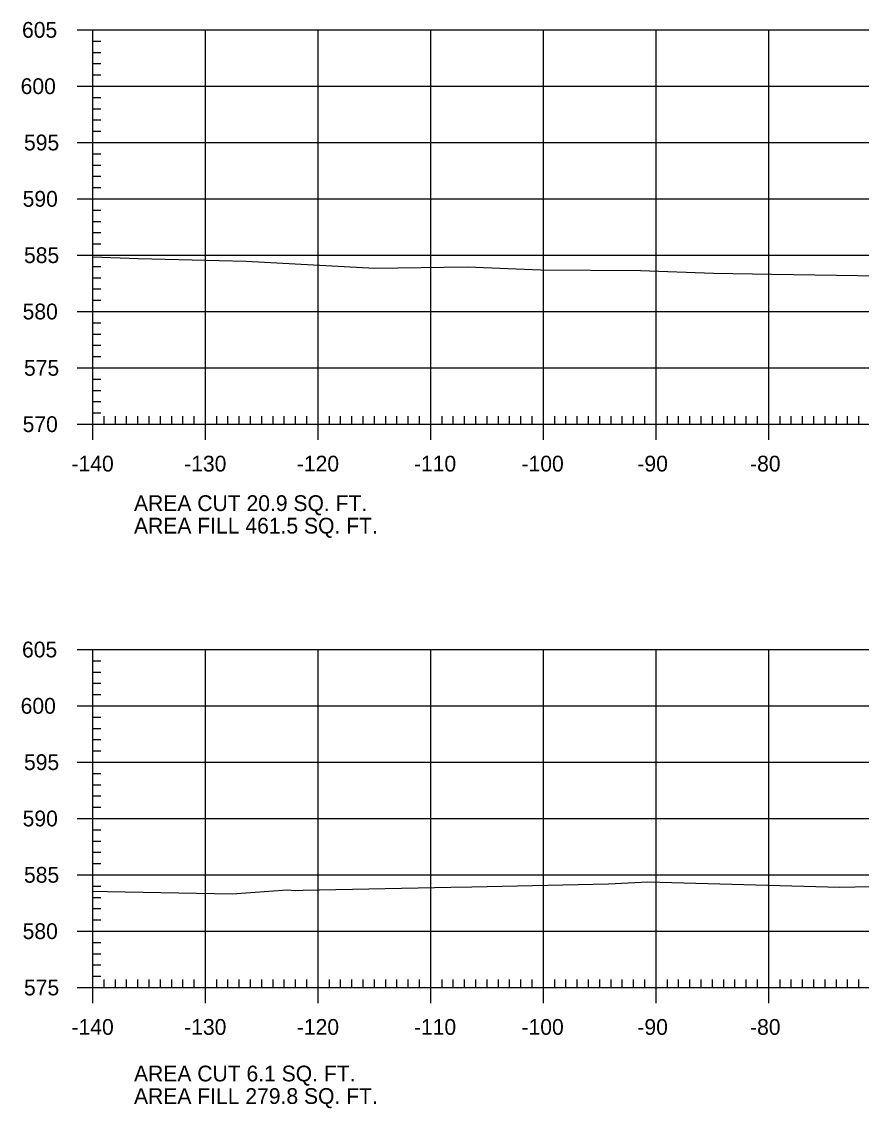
# Model space of a CAD drawing. Extents: x 961436 to 1372525, y 380079 to 2027791.
# Drawn here: x 1371476.2 to 1371550.7, y 380381.7 to 380478.1 of the extents above; entities that cross this region are included whole.
import ezdxf

# ---------------------------------------------------------------- set-up
doc = ezdxf.new("R2010")
doc.units = 0
for name, color, linetype in [('R_Axis', 7, 'Continuous'), ('R_Axis Annot', 7, 'Continuous'), ('R_Exist Surface', 7, 'Continuous'), ('R_Grid', 7, 'Continuous')]:
    doc.layers.add(name, color=color, linetype=linetype)

msp = doc.modelspace()

# ---------------------------------------------------------------- linework, layer by layer
at = {"layer": 'R_Axis'}
for p, q in [((1371481.067, 380477.397), (1371483.867, 380477.397)), ((1371482.467, 380442.397), (1371482.467, 380477.397)), ((1371482.467, 380476.397), (1371483.167, 380476.397)), ((1371482.467, 380475.397), (1371483.167, 380475.397)), ((1371482.467, 380474.397), (1371483.167, 380474.397)), ((1371482.467, 380473.397), (1371483.167, 380473.397)), ((1371481.067, 380472.397), (1371483.867, 380472.397)), ((1371482.467, 380471.397), (1371483.167, 380471.397)), ((1371482.467, 380470.397), (1371483.167, 380470.397)), ((1371482.467, 380469.397), (1371483.167, 380469.397)), ((1371482.467, 380468.397), (1371483.167, 380468.397)), ((1371481.067, 380467.397), (1371483.867, 380467.397)), ((1371482.467, 380466.397), (1371483.167, 380466.397)), ((1371482.467, 380465.397), (1371483.167, 380465.397)), ((1371482.467, 380464.397), (1371483.167, 380464.397)), ((1371482.467, 380463.397), (1371483.167, 380463.397)), ((1371481.067, 380462.397), (1371483.867, 380462.397)), ((1371482.467, 380461.397), (1371483.167, 380461.397)), ((1371482.467, 380460.397), (1371483.167, 380460.397)), ((1371482.467, 380459.397), (1371483.167, 380459.397)), ((1371482.467, 380458.397), (1371483.167, 380458.397)), ((1371481.067, 380457.397), (1371483.867, 380457.397)), ((1371482.467, 380456.397), (1371483.167, 380456.397)), ((1371482.467, 380455.397), (1371483.167, 380455.397)), ((1371482.467, 380454.397), (1371483.167, 380454.397)), ((1371482.467, 380453.397), (1371483.167, 380453.397)), ((1371481.067, 380452.397), (1371483.867, 380452.397)), ((1371482.467, 380451.397), (1371483.167, 380451.397)), ((1371482.467, 380450.397), (1371483.167, 380450.397)), ((1371482.467, 380449.397), (1371483.167, 380449.397)), ((1371482.467, 380448.397), (1371483.167, 380448.397)), ((1371481.067, 380447.397), (1371483.867, 380447.397)), ((1371482.467, 380446.397), (1371483.167, 380446.397)), ((1371482.467, 380445.397), (1371483.167, 380445.397)), ((1371482.467, 380444.397), (1371483.167, 380444.397)), ((1371482.467, 380440.997), (1371482.467, 380443.797)), ((1371482.467, 380443.397), (1371483.167, 380443.397)), ((1371483.467, 380442.397), (1371483.467, 380443.097)), ((1371484.467, 380442.397), (1371484.467, 380443.097)), ((1371485.467, 380442.397), (1371485.467, 380443.097)), ((1371486.467, 380442.397), (1371486.467, 380443.097)), ((1371487.467, 380442.397), (1371487.467, 380443.097)), ((1371488.467, 380442.397), (1371488.467, 380443.097)), ((1371489.467, 380442.397), (1371489.467, 380443.097)), ((1371490.467, 380442.397), (1371490.467, 380443.097)), ((1371491.467, 380442.397), (1371491.467, 380443.097)), ((1371492.467, 380440.997), (1371492.467, 380443.797)), ((1371493.467, 380442.397), (1371493.467, 380443.097)), ((1371494.467, 380442.397), (1371494.467, 380443.097)), ((1371495.467, 380442.397), (1371495.467, 380443.097)), ((1371496.467, 380442.397), (1371496.467, 380443.097)), ((1371497.467, 380442.397), (1371497.467, 380443.097)), ((1371498.467, 380442.397), (1371498.467, 380443.097)), ((1371499.467, 380442.397), (1371499.467, 380443.097)), ((1371500.467, 380442.397), (1371500.467, 380443.097)), ((1371501.467, 380442.397), (1371501.467, 380443.097)), ((1371502.467, 380440.997), (1371502.467, 380443.797)), ((1371503.467, 380442.397), (1371503.467, 380443.097)), ((1371504.467, 380442.397), (1371504.467, 380443.097)), ((1371505.467, 380442.397), (1371505.467, 380443.097)), ((1371506.467, 380442.397), (1371506.467, 380443.097)), ((1371507.467, 380442.397), (1371507.467, 380443.097)), ((1371508.467, 380442.397), (1371508.467, 380443.097)), ((1371509.467, 380442.397), (1371509.467, 380443.097)), ((1371510.467, 380442.397), (1371510.467, 380443.097)), ((1371511.467, 380442.397), (1371511.467, 380443.097)), ((1371512.467, 380440.997), (1371512.467, 380443.797)), ((1371513.467, 380442.397), (1371513.467, 380443.097)), ((1371514.467, 380442.397), (1371514.467, 380443.097)), ((1371515.467, 380442.397), (1371515.467, 380443.097)), ((1371516.467, 380442.397), (1371516.467, 380443.097)), ((1371517.467, 380442.397), (1371517.467, 380443.097)), ((1371518.467, 380442.397), (1371518.467, 380443.097)), ((1371519.467, 380442.397), (1371519.467, 380443.097)), ((1371520.467, 380442.397), (1371520.467, 380443.097)), ((1371521.467, 380442.397), (1371521.467, 380443.097)), ((1371522.467, 380440.997), (1371522.467, 380443.797)), ((1371523.467, 380442.397), (1371523.467, 380443.097)), ((1371524.467, 380442.397), (1371524.467, 380443.097)), ((1371525.467, 380442.397), (1371525.467, 380443.097)), ((1371526.467, 380442.397), (1371526.467, 380443.097)), ((1371527.467, 380442.397), (1371527.467, 380443.097)), ((1371528.467, 380442.397), (1371528.467, 380443.097)), ((1371529.467, 380442.397), (1371529.467, 380443.097)), ((1371530.467, 380442.397), (1371530.467, 380443.097)), ((1371531.467, 380442.397), (1371531.467, 380443.097)), ((1371532.467, 380440.997), (1371532.467, 380443.797)), ((1371533.467, 380442.397), (1371533.467, 380443.097)), ((1371534.467, 380442.397), (1371534.467, 380443.097)), ((1371535.467, 380442.397), (1371535.467, 380443.097)), ((1371536.467, 380442.397), (1371536.467, 380443.097)), ((1371537.467, 380442.397), (1371537.467, 380443.097)), ((1371538.467, 380442.397), (1371538.467, 380443.097)), ((1371539.467, 380442.397), (1371539.467, 380443.097)), ((1371540.467, 380442.397), (1371540.467, 380443.097)), ((1371541.467, 380442.397), (1371541.467, 380443.097)), ((1371542.467, 380440.997), (1371542.467, 380443.797)), ((1371543.467, 380442.397), (1371543.467, 380443.097)), ((1371544.467, 380442.397), (1371544.467, 380443.097)), ((1371545.467, 380442.397), (1371545.467, 380443.097)), ((1371546.467, 380442.397), (1371546.467, 380443.097)), ((1371547.467, 380442.397), (1371547.467, 380443.097)), ((1371548.467, 380442.397), (1371548.467, 380443.097)), ((1371549.467, 380442.397), (1371549.467, 380443.097)), ((1371550.467, 380442.397), (1371550.467, 380443.097)), ((1371481.067, 380442.397), (1371483.867, 380442.397)), ((1371482.467, 380442.397), (1371762.467, 380442.397)), ((1371481.067, 380422.397), (1371483.867, 380422.397)), ((1371482.467, 380392.397), (1371482.467, 380422.397)), ((1371482.467, 380421.397), (1371483.167, 380421.397)), ((1371482.467, 380420.397), (1371483.167, 380420.397)), ((1371482.467, 380419.397), (1371483.167, 380419.397)), ((1371482.467, 380418.397), (1371483.167, 380418.397)), ((1371481.067, 380417.397), (1371483.867, 380417.397)), ((1371482.467, 380416.397), (1371483.167, 380416.397)), ((1371482.467, 380415.397), (1371483.167, 380415.397)), ((1371482.467, 380414.397), (1371483.167, 380414.397)), ((1371482.467, 380413.397), (1371483.167, 380413.397)), ((1371481.067, 380412.397), (1371483.867, 380412.397)), ((1371482.467, 380411.397), (1371483.167, 380411.397)), ((1371482.467, 380410.397), (1371483.167, 380410.397)), ((1371482.467, 380409.397), (1371483.167, 380409.397)), ((1371482.467, 380408.397), (1371483.167, 380408.397)), ((1371481.067, 380407.397), (1371483.867, 380407.397)), ((1371482.467, 380406.397), (1371483.167, 380406.397)), ((1371482.467, 380405.397), (1371483.167, 380405.397)), ((1371482.467, 380404.397), (1371483.167, 380404.397)), ((1371482.467, 380403.397), (1371483.167, 380403.397)), ((1371481.067, 380402.397), (1371483.867, 380402.397)), ((1371482.467, 380401.397), (1371483.167, 380401.397)), ((1371482.467, 380400.397), (1371483.167, 380400.397)), ((1371482.467, 380399.397), (1371483.167, 380399.397)), ((1371482.467, 380398.397), (1371483.167, 380398.397)), ((1371481.067, 380397.397), (1371483.867, 380397.397)), ((1371482.467, 380396.397), (1371483.167, 380396.397)), ((1371482.467, 380395.397), (1371483.167, 380395.397)), ((1371482.467, 380394.397), (1371483.167, 380394.397)), ((1371482.467, 380390.997), (1371482.467, 380393.797)), ((1371492.467, 380390.997), (1371492.467, 380393.797)), ((1371502.467, 380390.997), (1371502.467, 380393.797)), ((1371512.467, 380390.997), (1371512.467, 380393.797)), ((1371522.467, 380390.997), (1371522.467, 380393.797)), ((1371532.467, 380390.997), (1371532.467, 380393.797)), ((1371542.467, 380390.997), (1371542.467, 380393.797)), ((1371482.467, 380393.397), (1371483.167, 380393.397)), ((1371483.467, 380392.397), (1371483.467, 380393.097)), ((1371484.467, 380392.397), (1371484.467, 380393.097)), ((1371485.467, 380392.397), (1371485.467, 380393.097)), ((1371486.467, 380392.397), (1371486.467, 380393.097)), ((1371487.467, 380392.397), (1371487.467, 380393.097)), ((1371488.467, 380392.397), (1371488.467, 380393.097)), ((1371489.467, 380392.397), (1371489.467, 380393.097)), ((1371490.467, 380392.397), (1371490.467, 380393.097)), ((1371491.467, 380392.397), (1371491.467, 380393.097)), ((1371493.467, 380392.397), (1371493.467, 380393.097)), ((1371494.467, 380392.397), (1371494.467, 380393.097)), ((1371495.467, 380392.397), (1371495.467, 380393.097)), ((1371496.467, 380392.397), (1371496.467, 380393.097)), ((1371497.467, 380392.397), (1371497.467, 380393.097)), ((1371498.467, 380392.397), (1371498.467, 380393.097)), ((1371499.467, 380392.397), (1371499.467, 380393.097)), ((1371500.467, 380392.397), (1371500.467, 380393.097)), ((1371501.467, 380392.397), (1371501.467, 380393.097)), ((1371503.467, 380392.397), (1371503.467, 380393.097)), ((1371504.467, 380392.397), (1371504.467, 380393.097)), ((1371505.467, 380392.397), (1371505.467, 380393.097)), ((1371506.467, 380392.397), (1371506.467, 380393.097)), ((1371507.467, 380392.397), (1371507.467, 380393.097)), ((1371508.467, 380392.397), (1371508.467, 380393.097)), ((1371509.467, 380392.397), (1371509.467, 380393.097)), ((1371510.467, 380392.397), (1371510.467, 380393.097)), ((1371511.467, 380392.397), (1371511.467, 380393.097)), ((1371513.467, 380392.397), (1371513.467, 380393.097)), ((1371514.467, 380392.397), (1371514.467, 380393.097)), ((1371515.467, 380392.397), (1371515.467, 380393.097)), ((1371516.467, 380392.397), (1371516.467, 380393.097)), ((1371517.467, 380392.397), (1371517.467, 380393.097)), ((1371518.467, 380392.397), (1371518.467, 380393.097)), ((1371519.467, 380392.397), (1371519.467, 380393.097)), ((1371520.467, 380392.397), (1371520.467, 380393.097)), ((1371521.467, 380392.397), (1371521.467, 380393.097)), ((1371523.467, 380392.397), (1371523.467, 380393.097)), ((1371524.467, 380392.397), (1371524.467, 380393.097)), ((1371525.467, 380392.397), (1371525.467, 380393.097)), ((1371526.467, 380392.397), (1371526.467, 380393.097)), ((1371527.467, 380392.397), (1371527.467, 380393.097)), ((1371528.467, 380392.397), (1371528.467, 380393.097)), ((1371529.467, 380392.397), (1371529.467, 380393.097)), ((1371530.467, 380392.397), (1371530.467, 380393.097)), ((1371531.467, 380392.397), (1371531.467, 380393.097)), ((1371533.467, 380392.397), (1371533.467, 380393.097)), ((1371534.467, 380392.397), (1371534.467, 380393.097)), ((1371535.467, 380392.397), (1371535.467, 380393.097)), ((1371536.467, 380392.397), (1371536.467, 380393.097)), ((1371537.467, 380392.397), (1371537.467, 380393.097)), ((1371538.467, 380392.397), (1371538.467, 380393.097)), ((1371539.467, 380392.397), (1371539.467, 380393.097)), ((1371540.467, 380392.397), (1371540.467, 380393.097)), ((1371541.467, 380392.397), (1371541.467, 380393.097)), ((1371543.467, 380392.397), (1371543.467, 380393.097)), ((1371544.467, 380392.397), (1371544.467, 380393.097)), ((1371545.467, 380392.397), (1371545.467, 380393.097)), ((1371546.467, 380392.397), (1371546.467, 380393.097)), ((1371547.467, 380392.397), (1371547.467, 380393.097)), ((1371548.467, 380392.397), (1371548.467, 380393.097)), ((1371549.467, 380392.397), (1371549.467, 380393.097)), ((1371550.467, 380392.397), (1371550.467, 380393.097)), ((1371481.067, 380392.397), (1371483.867, 380392.397)), ((1371482.467, 380392.397), (1371762.467, 380392.397))]:
    msp.add_line(p, q, dxfattribs=at)
at = {"layer": 'R_Exist Surface'}
for points in [[(1371482.467, 380457.243), (1371486.49, 380457.1), (1371496.083, 380456.872), (1371507.498, 380456.238), (1371515.7, 380456.348), (1371522.243, 380456.107), (1371531.074, 380456.052), (1371537.573, 380455.815), (1371542.727, 380455.714), (1371556.124, 380455.502)], [(1371482.467, 380400.955), (1371483.764, 380400.927), (1371494.837, 380400.724), (1371499.731, 380401.06), (1371500.461, 380401.019), (1371501.152, 380401.032), (1371514.248, 380401.303), (1371516.108, 380401.335), (1371528.254, 380401.584), (1371531.739, 380401.789), (1371548.788, 380401.294), (1371551.516, 380401.361)]]:
    msp.add_lwpolyline(points, dxfattribs=at)
at = {"layer": 'R_Grid'}
for p, q in [((1371482.467, 380477.397), (1371762.467, 380477.397)), ((1371482.467, 380442.397), (1371482.467, 380477.397)), ((1371492.467, 380442.397), (1371492.467, 380477.397)), ((1371502.467, 380442.397), (1371502.467, 380477.397)), ((1371512.467, 380442.397), (1371512.467, 380477.397)), ((1371522.467, 380442.397), (1371522.467, 380477.397)), ((1371532.467, 380442.397), (1371532.467, 380477.397)), ((1371542.467, 380442.397), (1371542.467, 380477.397)), ((1371482.467, 380472.397), (1371762.467, 380472.397)), ((1371482.467, 380467.397), (1371762.467, 380467.397)), ((1371482.467, 380462.397), (1371762.467, 380462.397)), ((1371482.467, 380457.397), (1371762.467, 380457.397)), ((1371482.467, 380452.397), (1371762.467, 380452.397)), ((1371482.467, 380447.397), (1371762.467, 380447.397)), ((1371482.467, 380442.397), (1371762.467, 380442.397)), ((1371482.467, 380422.397), (1371762.467, 380422.397)), ((1371482.467, 380392.397), (1371482.467, 380422.397)), ((1371492.467, 380392.397), (1371492.467, 380422.397)), ((1371502.467, 380392.397), (1371502.467, 380422.397)), ((1371512.467, 380392.397), (1371512.467, 380422.397)), ((1371522.467, 380392.397), (1371522.467, 380422.397)), ((1371532.467, 380392.397), (1371532.467, 380422.397)), ((1371542.467, 380392.397), (1371542.467, 380422.397)), ((1371482.467, 380417.397), (1371762.467, 380417.397)), ((1371482.467, 380412.397), (1371762.467, 380412.397)), ((1371482.467, 380407.397), (1371762.467, 380407.397)), ((1371482.467, 380402.397), (1371762.467, 380402.397)), ((1371482.467, 380397.397), (1371762.467, 380397.397)), ((1371482.467, 380392.397), (1371762.467, 380392.397))]:
    msp.add_line(p, q, dxfattribs=at)

# ---------------------------------------------------------------- texts
at = {"layer": 'R_Axis Annot'}
for s, p in [('605', (1371476.184, 380476.697)), ('600', (1371476.062, 380471.697)), ('595', (1371476.36, 380466.697)), ('590', (1371476.239, 380461.697)), ('585', (1371476.36, 380456.697)), ('580', (1371476.239, 380451.697)), ('575', (1371476.36, 380446.697)), ('570', (1371476.239, 380441.697)), ('-140', (1371480.577, 380438.197)), ('-130', (1371490.577, 380438.197)), ('-120', (1371500.577, 380438.197)), ('-110', (1371510.973, 380438.197)), ('-100', (1371520.521, 380438.197)), ('-90', (1371530.808, 380438.197)), ('-80', (1371540.808, 380438.197)), ('AREA CUT 20.9 SQ. FT.', (1371486.124, 380434.688)), ('AREA FILL 461.5 SQ. FT.', (1371486.124, 380432.688)), ('605', (1371476.184, 380421.697)), ('600', (1371476.062, 380416.697)), ('595', (1371476.36, 380411.697)), ('590', (1371476.239, 380406.697)), ('585', (1371476.36, 380401.697)), ('580', (1371476.239, 380396.697)), ('575', (1371476.36, 380391.697)), ('-140', (1371480.577, 380388.197)), ('-130', (1371490.577, 380388.197)), ('-120', (1371500.577, 380388.197)), ('-110', (1371510.973, 380388.197)), ('-100', (1371520.521, 380388.197)), ('-90', (1371530.808, 380388.197)), ('-80', (1371540.808, 380388.197)), ('AREA CUT 6.1 SQ. FT.', (1371486.124, 380384.062)), ('AREA FILL 279.8 SQ. FT.', (1371486.124, 380382.062))]:
    msp.add_text(s, height=1.4, dxfattribs=at).set_placement(p)

doc.saveas('drawing.dxf')
